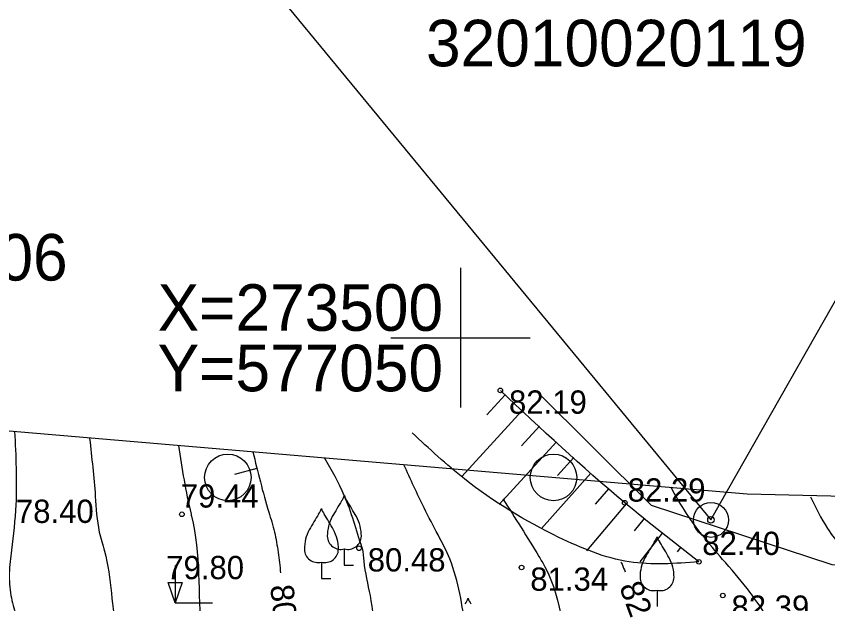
# Model space of a CAD drawing. Extents: x 576692 to 577659, y 273254 to 273799.
# Drawn here: x 577040.45 to 577057.89, y 273494.28 to 273506.91 of the extents above; entities that cross this region are included whole.
import ezdxf

# ---------------------------------------------------------------- set-up
doc = ezdxf.new("R2010")
doc.units = 0
for name, color, linetype in [('BUVE_BDET_####_####_#', 7, 'Continuous'), ('BUVE_EKAS_BPAL_####_#', 7, 'Continuous'), ('BUVE_EKAS_RAKS_TKST_#', 7, 'Continuous'), ('CELI_TAKA_####_####_#', 7, 'Continuous'), ('CKOM_ELEM_####_####_#', 7, 'Continuous'), ('CKOM_ZEMJ_####_TKST_#', 7, 'Continuous'), ('GAZE_ELEM_####_####_#', 7, 'Continuous'), ('GEOD_ELEM_####_TKST_#', 7, 'Continuous'), ('GEOD_SITP_####_TKST_#', 7, 'Continuous'), ('HIDT_REZV_####_TKST_#', 7, 'Continuous'), ('LKAN_ELEM_PAST_TKST_#', 7, 'Continuous'), ('RELJ_ELEM_####_####_#', 7, 'Continuous'), ('RELJ_HORZ_PAMT_####_#', 7, 'Continuous'), ('SAKT_ELEM_####_####_#', 7, 'Continuous'), ('SILT_VADP_UDEN_####_#', 7, 'Continuous')]:
    doc.layers.add(name, color=color, linetype=linetype)

msp = doc.modelspace()

# ---------------------------------------------------------------- linework, layer by layer
at = {"layer": 'BUVE_BDET_####_####_#'}
msp.add_lwpolyline([(577090.308, 273494.934), (577065.677, 273495.083), (577057.991, 273495.121), (577054.103, 273496.396), (577051.621, 273498.87)], dxfattribs=at)
at = {"layer": 'BUVE_EKAS_RAKS_TKST_#'}
for radius in [0.375, 0.0702]:
    msp.add_circle((577055.384, 273496.087), radius, dxfattribs=at)
at = {"layer": 'CELI_TAKA_####_####_#'}
msp.add_lwpolyline([(577034.918, 273498.457), (577056.159, 273496.649), (577089.41, 273495.849), (577091.53, 273498.895), (577133.743, 273488.404), (577156.263, 273478.496), (577168.613, 273472.255), (577170.64, 273473.445), (577173.767, 273472.475), (577175.353, 273468.597), (577186.541, 273460.401)], dxfattribs=at)
at = {"layer": 'CKOM_ELEM_####_####_#'}
for p, q in [((577050, 273501.5), (577050, 273500)), ((577048.5, 273500), (577050, 273500)), ((577050, 273500), (577050, 273498.5)), ((577050, 273500), (577051.5, 273500))]:
    msp.add_line(p, q, dxfattribs=at)
at = {"layer": 'GAZE_ELEM_####_####_#'}
for p, q in [((577050.959, 273498.775), (577050.568, 273498.347)), ((577051.328, 273498.438), (577050.028, 273497.018)), ((577051.697, 273498.1), (577051.312, 273497.68)), ((577052.066, 273497.763), (577050.833, 273496.415)), ((577052.435, 273497.425), (577052.086, 273497.044)), ((577052.805, 273497.089), (577051.743, 273495.904)), ((577053.18, 273496.758), (577052.892, 273496.428)), ((577053.559, 273496.432), (577052.706, 273495.419)), ((577053.945, 273496.114), (577053.732, 273495.85)), ((577054.336, 273495.804), (577053.853, 273495.186)), ((577054.73, 273495.495), (577054.658, 273495.403)), ((577055.123, 273495.186), (577055.122, 273495.185)), ((577055.123, 273495.186), (577055.122, 273495.185))]:
    msp.add_line(p, q, dxfattribs=at)
msp.add_spline([(577055.123, 273495.186), (577053.531, 273496.455), (577050.857, 273498.869)], degree=3, dxfattribs=at)
at = {"layer": 'GEOD_ELEM_####_TKST_#'}
msp.add_line((577045.148, 273497.072), (577045.631, 273497.199), dxfattribs=at)
for points in [[(577045.539, 273497.553), (577045.879, 273496.256), (577046.003, 273495.826), (577046.046, 273495.608), (577046.081, 273495.389), (577046.134, 273494.948)], [(577053.449, 273495.185), (577053.472, 273495.133), (577053.542, 273494.972)]]:
    msp.add_spline(points, degree=3, dxfattribs=at)
at = {"layer": 'GEOD_SITP_####_TKST_#'}
for points in [[(577040.417, 273497.984), (577040.443, 273496.414), (577040.349, 273495.435), (577040.303, 273494.945), (577040.338, 273494.463), (577040.447, 273494.041), (577040.681, 273493.533), (577040.956, 273493.045), (577041.212, 273492.554), (577041.391, 273492.035), (577041.869, 273489.806), (577042.219, 273488.106), (577043.253, 273485.655), (577044.552, 273483.727), (577046.014, 273482.091), (577046.783, 273481.259), (577048.185, 273479.669), (577049.877, 273477.803), (577050.537, 273477.241), (577051.005, 273476.925)], [(577042.029, 273497.834), (577042.151, 273496.597), (577042.237, 273495.827), (577042.348, 273495.417), (577042.612, 273493.606), (577042.788, 273492.796), (577043.115, 273489.781), (577043.201, 273489.359), (577044.789, 273485.486), (577045.201, 273484.828), (577045.704, 273484.253), (577048.035, 273481.688), (577050.426, 273478.992), (577050.95, 273478.531), (577051.921, 273477.93), (577052.272, 273477.718)], [(577043.941, 273497.684), (577044.209, 273496.212), (577044.22, 273496.167), (577044.424, 273493.678), (577044.463, 273493.254), (577044.518, 273492.64), (577045.015, 273489.58), (577046.095, 273486.348), (577046.819, 273485.018), (577047.507, 273484.144), (577049.312, 273482.126), (577050.283, 273481.068), (577052.054, 273479.561), (577053.64, 273478.59)], [(577057.125, 273480.459), (577056.46, 273480.606), (577054.796, 273481.39), (577053.704, 273482.242), (577052.56, 273483.243), (577051.583, 273484.184), (577051.027, 273484.948), (577048.982, 273488.708), (577048.632, 273489.635), (577048.414, 273490.932), (577048.235, 273492.614), (577048.064, 273494.459), (577047.93, 273495.199), (577047.891, 273495.471), (577047.885, 273495.49), (577047.504, 273496.611), (577047.08, 273497.422)], [(577062.362, 273482.006), (577061.261, 273482.097), (577059.812, 273482.302), (577058.232, 273482.54), (577057.758, 273482.579), (577057.281, 273482.578), (577056.803, 273482.575), (577056.326, 273482.603), (577055.991, 273482.736), (577055.398, 273483.233), (577054.855, 273483.753), (577053.846, 273484.86), (577051.962, 273487.19), (577051.785, 273487.505), (577050.671, 273490.629), (577050.323, 273492.192), (577050.109, 273493.729), (577049.77, 273495.247), (577049.518, 273495.769), (577049.219, 273496.343), (577048.786, 273497.272)], [(577083.085, 273488.059), (577082.621, 273488.121), (577081.819, 273488.035), (577080.424, 273487.844), (577079.645, 273487.791), (577078.503, 273487.807), (577077.332, 273487.888), (577075.684, 273487.97), (577071.896, 273487.997), (577071.538, 273488.008), (577070.762, 273488.072), (577067.637, 273488.369), (577067.095, 273488.429), (577064.982, 273488.853), (577060.24, 273490.561), (577058.756, 273491.376), (577057.68, 273492.354), (577057.319, 273492.874), (577056.977, 273493.403), (577056.637, 273493.933), (577056.282, 273494.451), (577056.161, 273494.614), (577055.635, 273495.238), (577054.815, 273496.293), (577054.526, 273496.789)], [(577050.913, 273496.54), (577051.688, 273495.298), (577051.814, 273495.08), (577052.347, 273492.651), (577052.506, 273491.712), (577052.545, 273491.542), (577052.693, 273491.186), (577055.51, 273486.164), (577055.858, 273485.703), (577056.396, 273485.401), (577057.886, 273485.073), (577057.994, 273485.052), (577058.256, 273484.997), (577060.309, 273484.545), (577063.226, 273484.152), (577066.402, 273484.015)], [(577057.525, 273496.583), (577057.888, 273495.904), (577058.202, 273495.499), (577058.434, 273495.269), (577059.507, 273494.393), (577059.751, 273494.174), (577060.048, 273493.951), (577063.139, 273492.63), (577064.769, 273492.21), (577067.223, 273491.692), (577068.144, 273491.504), (577072.333, 273490.725), (577072.867, 273490.661), (577074.61, 273490.57), (577078.565, 273490.563), (577081.127, 273490.67), (577084.148, 273490.586), (577084.254, 273490.573), (577084.372, 273490.6), (577084.484, 273490.638), (577084.781, 273490.685), (577086.299, 273490.897)]]:
    msp.add_spline(points, degree=3, dxfattribs=at)
at = {"layer": 'LKAN_ELEM_PAST_TKST_#'}
for p, q in [((577047.504, 273495.463), (577047.504, 273495.111)), ((577043.869, 273495.107), (577043.869, 273494.307)), ((577047.011, 273495.182), (577047.011, 273494.83)), ((577047.504, 273495.111), (577047.704, 273495.111)), ((577047.011, 273494.83), (577047.211, 273494.83)), ((577054.225, 273494.578), (577054.225, 273494.226)), ((577043.869, 273494.307), (577044.669, 273494.307))]:
    msp.add_line(p, q, dxfattribs=at)
for centre in [(577045, 273497), (577052, 273497)]:
    msp.add_circle(centre, 0.5, dxfattribs=at)
for centre, radius, start, end in [((577060.129, 273488.715), 14.88, 148.4844, 149.9901), ((577047.087, 273496.749), 0.439, 324.3837, 341.712), ((577047.921, 273496.749), 0.439, 198.288, 215.6163), ((577034.879, 273488.715), 14.88, 30.0099, 31.5156), ((577046.594, 273496.468), 0.439, 324.3837, 341.712), ((577047.428, 273496.468), 0.439, 198.288, 215.6163), ((577059.636, 273488.434), 14.88, 148.4844, 149.9901), ((577034.386, 273488.434), 14.88, 30.0099, 31.5156), ((577048.028, 273495.736), 0.89, 151.757, 179.9138), ((577046.98, 273495.736), 0.89, 0.0862, 28.243), ((577047.535, 273495.455), 0.89, 151.757, 179.9138), ((577046.487, 273495.455), 0.89, 0.0862, 28.243), ((577047.428, 273495.742), 0.29, 181.0782, 285.2823), ((577047.58, 273495.742), 0.29, 254.7177, 358.9218), ((577053.808, 273495.864), 0.439, 324.3837, 341.712), ((577054.642, 273495.864), 0.439, 198.288, 215.6163), ((577046.935, 273495.461), 0.29, 181.0782, 285.2823), ((577047.087, 273495.461), 0.29, 254.7177, 358.9218), ((577066.85, 273487.83), 14.88, 148.4844, 149.9901), ((577041.6, 273487.83), 14.88, 30.0099, 31.5156), ((577054.749, 273494.851), 0.89, 151.757, 179.9138), ((577053.701, 273494.851), 0.89, 0.0862, 28.243), ((577054.149, 273494.857), 0.29, 181.0782, 285.2823), ((577054.301, 273494.857), 0.29, 254.7177, 358.9218), ((577049.747, 273494.541), 0.439, 324.3837, 341.712), ((577050.581, 273494.541), 0.439, 198.288, 215.6163)]:
    msp.add_arc(centre, radius, start, end, dxfattribs=at)
at = {"layer": 'RELJ_ELEM_####_####_#'}
msp.add_lwpolyline([(577043.719, 273494.74), (577044.019, 273494.74), (577043.869, 273494.307)], close=True, dxfattribs=at)
for centre in [(577050.857, 273498.869), (577053.531, 273496.455), (577044.012, 273496.207), (577047.821, 273495.479), (577051.315, 273495.064), (577055.123, 273495.186), (577055.639, 273494.463)]:
    msp.add_circle(centre, 0.05, dxfattribs=at)
at = {"layer": 'SAKT_ELEM_####_####_#'}
msp.add_spline([(577055.123, 273495.186), (577053.627, 273495.186), (577052.117, 273495.712), (577050.087, 273496.966), (577048.962, 273497.959)], degree=3, dxfattribs=at)
at = {"layer": 'SILT_VADP_UDEN_####_#'}
msp.add_lwpolyline([(576978.221, 273570.568), (576969.56, 273570.99), (576960.32, 273539.8), (576960.15, 273534.54), (576956.49, 273534.78), (576954.98, 273513.09), (576972.68, 273506.2), (577024.96, 273501.23), (577028.05, 273514.57), (577031.756, 273524.733), (577055.384, 273496.087), (577061.73, 273507.256)], dxfattribs=at)

# ---------------------------------------------------------------- texts
at = {"layer": 'BUVE_EKAS_BPAL_####_#'}
for s, p in [('32010020119', (577049.26, 273505.833)), ('32010020106', (577033.376, 273501.23))]:
    msp.add_text(s, height=1, dxfattribs=at).set_placement(p)
at = {"layer": 'CKOM_ZEMJ_####_TKST_#'}
for s, p in [('X=273500', (577043.491, 273500.15)), ('Y=577050', (577043.491, 273498.85))]:
    msp.add_text(s, height=1, dxfattribs=at).set_placement(p)
at = {"layer": 'HIDT_REZV_####_TKST_#'}
for s, p in [(' 82.19', (577050.857, 273498.369)), (' 79.44', (577043.803, 273496.352)), (' 82.29', (577053.409, 273496.48)), (' 78.40', (577040.259, 273496.022)), (' 82.40', (577055.011, 273495.333)), (' 80.48', (577047.821, 273494.979)), (' 79.80', (577043.49, 273494.813)), (' 81.34', (577051.315, 273494.564)), (' 82.39', (577055.639, 273493.963))]:
    msp.add_text(s, height=0.5, dxfattribs=at).set_placement(p)
at = {"layer": 'RELJ_HORZ_PAMT_####_#'}
for s, rotation, p in [('82', 290.355, (577053.407, 273494.655)), ('80', 275.9741, (577045.91, 273494.673))]:
    msp.add_text(s, height=0.5, rotation=rotation, dxfattribs=at).set_placement(p)

doc.saveas('drawing.dxf')
